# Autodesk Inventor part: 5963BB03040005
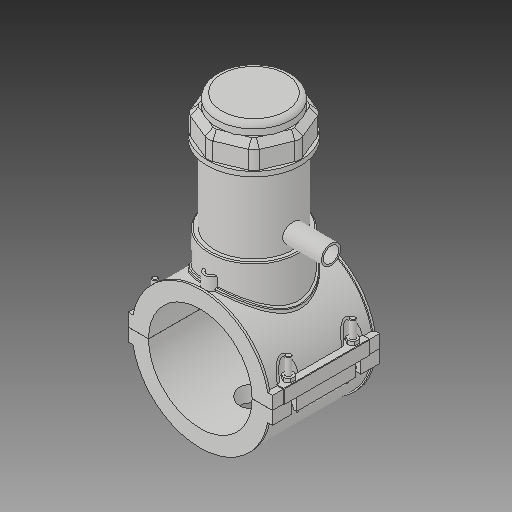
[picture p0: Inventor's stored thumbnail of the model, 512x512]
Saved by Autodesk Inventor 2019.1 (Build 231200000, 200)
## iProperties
Created: 2017-07
Part Number: 5963BB03040005
Material: Generic
Description: PLASSON TAPPING SADDLE 4''IPS x 1 1/2''IPS
Document SubType Name: Modeling
Designer: KIM
Mass: 1712.7 g
Surface Area: 2671.49 cm^2
Volume: 1712.7 cm^3
Density: 1 g/cm^3
Appearance: Default
Author: KIM
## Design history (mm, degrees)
derived "5963B.ipt"
feature "Solid1::5963B.ipt"
feature "Solid2::5963B.ipt"
feature "Solid4::5963B.ipt"
feature "Solid5::5963B.ipt"
tag "TaggingFeature1"
body "Solid1"
body "Solid2"
other parameters: "d0" = 114.1, "d2" = 159.004, "d3" = 28.525, "d4" = 118.11, "d5" = 0, "d6" = 0.1, "d8" = 0, "d19" = 6, "d20" = 6, "d21" = 70.866, "d23" = 0, "d24" = 35.433, "d26" = 0, "d29" = 3, "d30" = 38.03333, "d31" = 6, "d32" = 0, "d33" = 0, "d34" = 0.6, "d40" = 77.1316, "d41" = 102.69, "d43" = 0, "d45" = 0, "d47" = 145.031, "d70" = 15, "d72" = 0, "d73" = 6, "d75" = 5, "d76" = 0, "d77" = 5.705, "d78" = 87.05, "d79" = 15, "d80" = 47.244, "d82" = 5 deg, "d84" = 4, "d85" = 14, "d86" = 0, "d87" = 3, "d88" = 0, "d89" = 1, "d90" = 1, "d91" = 94.488, "d92" = 0, "d93" = 0.5, "d94" = 60.05263, "d96" = 151.2966, "d97" = 2.3622, "d98" = 0, "d102" = 1.141, "d120" = 140 deg, "d121" = 24.228, "d122" = 20 deg, "d123" = 296.66, "d124" = 88.998, "d126" = 0, "d143" = 117.523, "d145" = 26.33077, "d149" = 1.7115, "d150" = 28.96385, "d153" = 118.11, "d154" = 0, "d156" = 74.165, "d157" = 160 deg, "d159" = 6.846, "d161" = 1.7115, "d162" = 70.866, "d163" = 0, "d164" = 57.05, "d167" = 11.41, "d168" = 72.3561, "d170" = 3.2805, "d172" = 0, "d173" = 1, "d175" = 57.05, "d176" = 20 deg, "d177" = 7.987, "d178" = 34.23, "d180" = 0, "d183" = 13.692, "d184" = 6.3896, "d185" = 38.38575, "d186" = 38.38575, "d187" = 74.165, "d188" = 10.269, "d189" = 7.987, "d190" = 0, "d191" = 111.2475, "d193" = 6.1236, "d194" = 4.13385, "d195" = 90 deg, "d197" = 0, "d199" = 0, "d200" = 17.115, "d202" = 0, "d203" = 177.038, "d204" = 97.5555, "d205" = 71.883, "d206" = 87.2865, "d207" = 132.7785, "d208" = 138.08964, "d209" = 164.64534, "d210" = 88.3134, "d211" = 102.69, "d212" = 82.152, "d213" = 48.9816, "d216" = 0, "d217" = 11.41, "d218" = 5.705, "d219" = 1.141, "d222" = 114.1, "d224" = 0, "d230" = 6.846, "d233" = 6, "d236" = 79.502, "d237" = 35.433, "d238" = 6.02433, "d240" = 35.433, "d241" = 35.433, "d242" = 35.433, "d243" = 6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
